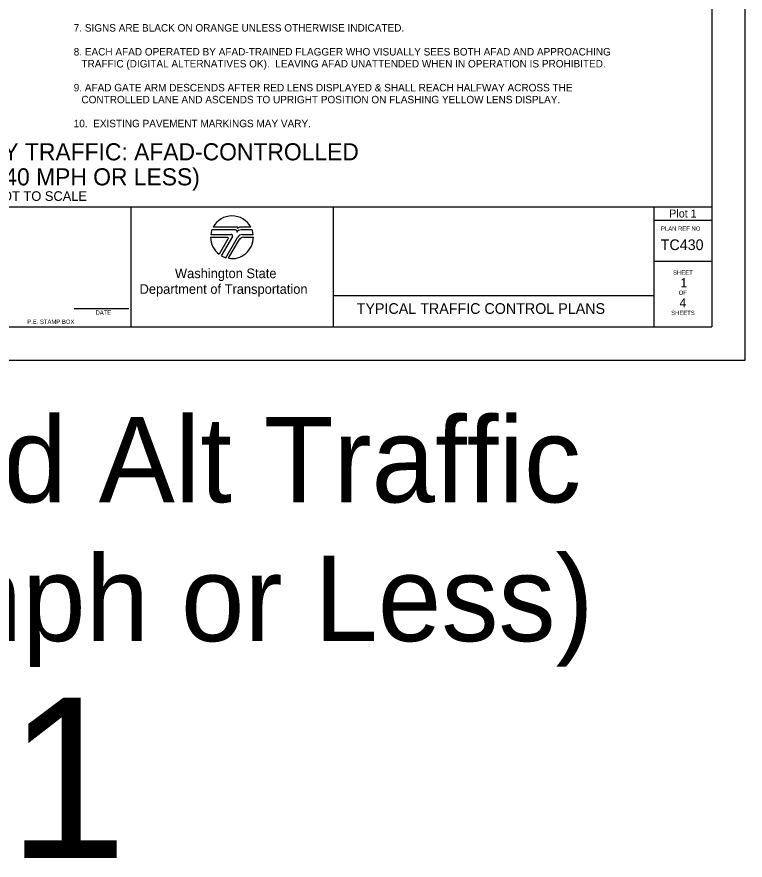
# Model space of a CAD drawing. Extents: x 99999.1 to 100095.7, y 99995 to 100010.7.
# Drawn here: x 100009.24 to 100016.06, y 99995.01 to 100002.9 of the extents above; entities that cross this region are included whole.
import ezdxf

# ---------------------------------------------------------------- set-up
doc = ezdxf.new("R2010")
doc.units = 0
for name, color, linetype in [('SH_DE_DetailHeading1Text', 7, 'Continuous'), ('SH_GI_GeneralNotesBodyText', 7, 'Continuous'), ('SH_GI_PlotLimits', 7, 'Continuous'), ('SH_GI_SheetBorder', 7, 'Continuous'), ('SH_GI_SheetLocationText', 7, 'Continuous'), ('SH_GI_SheetTextInCells', 7, 'Continuous'), ('SH_GI_TitleBlockText', 7, 'Continuous'), ('SH_GI_WSDOTLogo', 7, 'Continuous')]:
    doc.layers.add(name, color=color, linetype=linetype)

msp = doc.modelspace()

# ---------------------------------------------------------------- linework, layer by layer
at = {"layer": 'SH_GI_PlotLimits'}
msp.add_lwpolyline([(99999.0625, 99999.6875), (100016.0625, 99999.6875), (100016.0625, 100010.6875), (99999.0625, 100010.6875)], close=True, dxfattribs=at)
at = {"layer": 'SH_GI_SheetBorder'}
for p, q in [((100015.75, 100010.375), (100015.75, 100000)), ((100000, 100001.1259), (100015.75, 100001.1259)), ((100010.3089, 100001.1259), (100010.3089, 100000)), ((100012.2055, 100001.1259), (100012.2055, 100000)), ((100015.2079, 100001.1259), (100015.2079, 100000)), ((100015.2079, 100001.0008), (100015.75, 100001.0008)), ((100015.2079, 100000.6176), (100015.75, 100000.6176)), ((100012.2055, 100000.2955), (100015.2079, 100000.2955)), ((100009.7797, 100000.1733), (100010.2914, 100000.1733)), ((100000, 100000), (100015.75, 100000))]:
    msp.add_line(p, q, dxfattribs=at)
at = {"layer": 'SH_GI_WSDOTLogo'}
for p, q in [((100011.303, 100000.9354), (100011.0815, 100000.9354)), ((100011.433, 100000.9354), (100011.3351, 100000.9354)), ((100011.059, 100000.8661), (100011.2496, 100000.8661)), ((100011.2894, 100000.9094), (100011.0697, 100000.9094)), ((100011.261, 100000.8464), (100011.1567, 100000.6672)), ((100011.343, 100000.9094), (100011.3429, 100000.9094)), ((100011.4448, 100000.9094), (100011.343, 100000.9094)), ((100011.3558, 100000.8661), (100011.4555, 100000.8661)), ((100011.0572, 100000.84), (100011.2148, 100000.84)), ((100011.222, 100000.8277), (100011.1364, 100000.6807)), ((100011.1989, 100000.6487), (100011.3089, 100000.839)), ((100011.2244, 100000.6428), (100011.3242, 100000.8156)), ((100011.3655, 100000.8394), (100011.4572, 100000.8394))]:
    msp.add_line(p, q, dxfattribs=at)
for centre, radius, start, end in [((100011.2572, 100000.84), 0.2, 28.47865, 151.53204), ((100011.303, 100000.9263), 0.00903, 329.87418, 90.00328), ((100011.3352, 100000.9066), 0.0287, 90.00721, 148.16763), ((100011.2572, 100000.84), 0.2, 159.69598, 172.50569), ((100011.2497, 100000.853), 0.0131, 329.76834, 90), ((100011.2894, 100000.8946), 0.0148, 327.8418, 89.99855), ((100011.3429, 100000.861), 0.0484, 89.99529, 147.82376), ((100011.3558, 100000.8119), 0.0542, 90, 149.99738), ((100011.2572, 100000.84), 0.2, 7.49431, 20.29406), ((100011.2572, 100000.84), 0.2, 179.99864, 232.84327), ((100011.2149, 100000.8318), 0.0082, 329.74356, 90), ((100011.2572, 100000.84), 0.2, 260.54554, 359.80857), ((100011.3654, 100000.7918), 0.0476, 90, 150.05432), ((100011.2572, 100000.84), 0.2, 239.79292, 253.0448)]:
    msp.add_arc(centre, radius, start, end, dxfattribs=at)

# ---------------------------------------------------------------- texts
at = {"layer": 'SH_DE_DetailHeading1Text'}
for s, height, p in [('ALTERNATING 1-LANE, 2-WAY TRAFFIC: AFAD-CONTROLLED', 0.16, (100006.156, 100001.5606)), ('(HIGHWAYS, 40 MPH OR LESS)', 0.16, (100007.7701, 100001.3259)), ('NOT TO SCALE', 0.09, (100009.0168, 100001.1809))]:
    msp.add_text(s, height=height, rotation=360, dxfattribs=at).set_placement(p)
at = {"layer": 'SH_GI_GeneralNotesBodyText'}
for s, p in [('7. SIGNS ARE BLACK ON ORANGE UNLESS OTHERWISE INDICATED.', (100009.7751, 100002.7666)), ('8. EACH AFAD OPERATED BY AFAD-TRAINED FLAGGER WHO VISUALLY SEES BOTH AFAD AND APPROACHING ', (100009.7751, 100002.5426)), ('TRAFFIC (DIGITAL ALTERNATIVES OK).  LEAVING AFAD UNATTENDED WHEN IN OPERATION IS PROHIBITED.', (100009.8473, 100002.4306)), ('9. AFAD GATE ARM DESCENDS AFTER RED LENS DISPLAYED & SHALL REACH HALFWAY ACROSS THE ', (100009.7751, 100002.2066)), ('CONTROLLED LANE AND ASCENDS TO UPRIGHT POSITION ON FLASHING YELLOW LENS DISPLAY.', (100009.8473, 100002.0946)), ('10.  EXISTING PAVEMENT MARKINGS MAY VARY.', (100009.7751, 100001.8706))]:
    msp.add_text(s, height=0.07, rotation=360, dxfattribs=at).set_placement(p)
at = {"layer": 'SH_GI_SheetBorder'}
msp.add_text('PLAN REF NO', height=0.040032, dxfattribs=at).set_placement((100015.2747, 100000.9008))
at = {"layer": 'SH_GI_SheetLocationText'}
for s, height, p in [('Plot 1', 0.075, (100015.3518, 100001.025)), ('AFAD-Controlled Alt Traffic', 0.8, (100001.6258, 99998.3571)), ('(Highways, 40 mph or Less)', 0.8, (100001.3256, 99997.0571)), ('Plot 1', 1.5, (100005.1448, 99995.0267))]:
    msp.add_text(s, height=height, dxfattribs=at).set_placement(p)
at = {"layer": 'SH_GI_SheetTextInCells'}
for s, height, p in [('Washington State', 0.090072, (100010.7229, 100000.4571)), ('SHEET', 0.04003, (100015.3877, 100000.4896)), ('Department of Transportation', 0.090072, (100010.3916, 100000.3101)), ('OF', 0.04003, (100015.4406, 100000.3008)), ('DATE', 0.04003, (100009.9794, 100000.1141)), ('SHEETS', 0.04003, (100015.3698, 100000.112)), ('P.E. STAMP BOX', 0.040032, (100009.339, 100000.0286))]:
    msp.add_text(s, height=height, dxfattribs=at).set_placement(p)
at = {"layer": 'SH_GI_TitleBlockText'}
for s, height, p in [('TC430', 0.1, (100015.2718, 100000.72)), ('1', 0.085, (100015.4566, 100000.3723)), ('TYPICAL TRAFFIC CONTROL PLANS', 0.1, (100012.4251, 100000.1224)), ('4', 0.085, (100015.4485, 100000.1843))]:
    msp.add_text(s, height=height, dxfattribs=at).set_placement(p)

doc.saveas('drawing.dxf')
